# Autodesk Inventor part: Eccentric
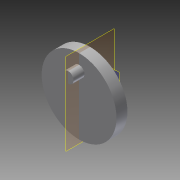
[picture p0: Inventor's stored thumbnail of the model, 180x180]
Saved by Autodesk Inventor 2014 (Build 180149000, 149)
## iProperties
Created: 2008-06
Part Number: Eccentric
Document SubType Name: Modeling
Designer: tangg
Density: 7.85 g/cm^3
Mass: 10.8718 g
Surface Area: 44.2672 cm^2
Volume: 10.8718 cm^3
Stock Number: Eccentric
Material: Steel
Appearance: Steel
Author: tangg
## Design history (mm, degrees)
sketch "Sketch1"
  geometry: C1 r 21.726 at (0, 0); 1 further point
  constraints: 1 centre point, 1 coincident
extrude "Extrusion1" new body sketch "Sketch1" distance "d0" = 6.35; taper "d1" = 0 deg
sketch "Sketch2"
  geometry: C1 r 3.175 at (0, 12.7); 1 further point
  constraints: 1 centre point
  dimensions: "d4" = 6.35 diameter of C1
extrude "Extrusion2" join sketch "Sketch2" distance "d2" = 6.35; taper "d3" = 0 deg
sketch "Sketch5"
  geometry: C1 r 3.175 at (0, 0); C2 r 8.542 at (0, 0); 1 further point
  constraints: 2 centre point, 1 coincident
workplane "Work Plane3"
extrude "Extrusion5" join sketch "Sketch5" distance "d9" = 6.35; taper "d10" = 0 deg
sketch "Sketch6"
  geometry: C1 r 3.175 at (0, 0); 3 further points
  constraints: 2 horizontal alignment, 1 centre point, 4 other
extrude "Extrusion4" join sketch "Sketch6" distance "d7" = 6.35; taper "d8" = 0 deg
sketch "Sketch7"
  geometry: C1 r 3.175 at (0, 0) reference; 3 further points
  constraints: 2 horizontal alignment
  node "Projected Loop1"
body "Solid1"
